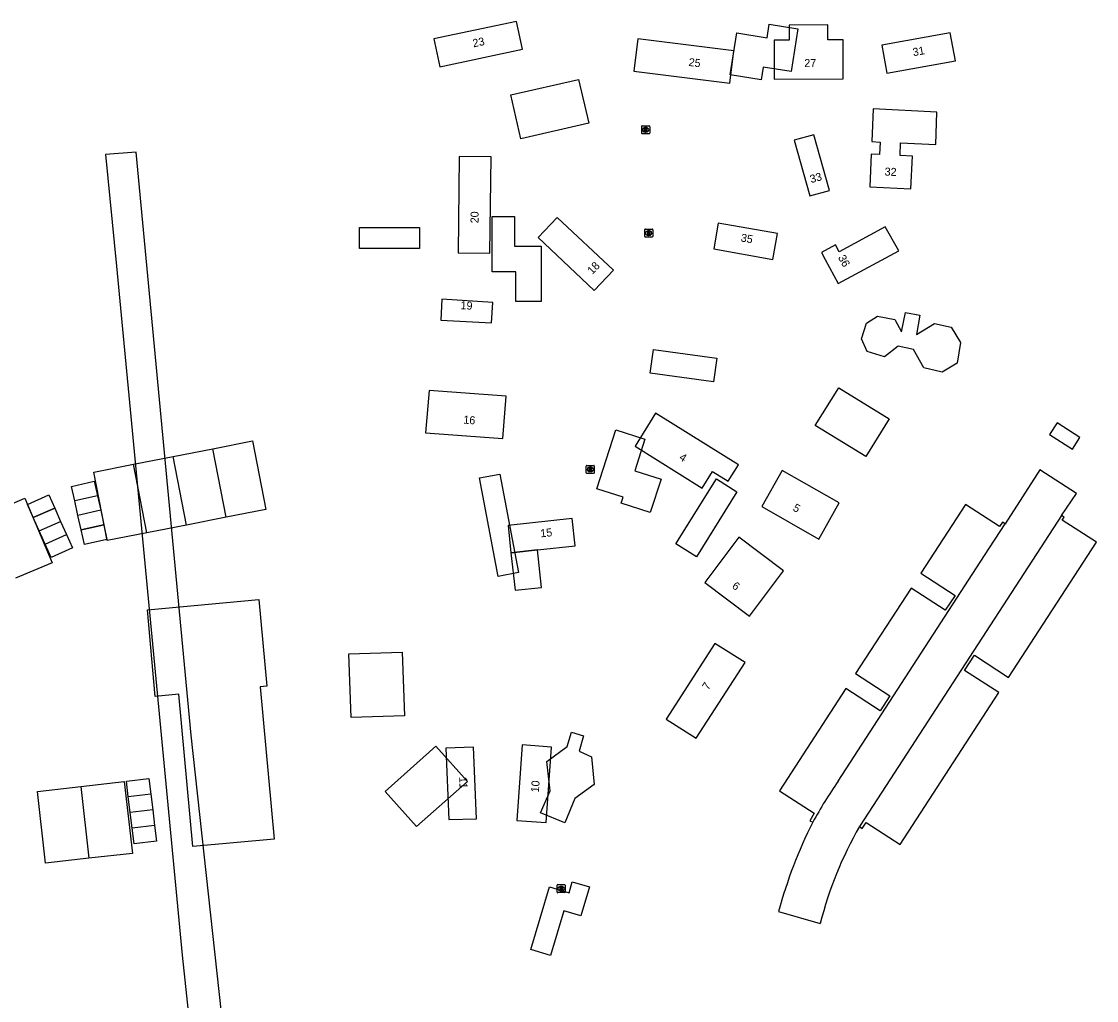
# Model space of a CAD drawing. Extents: x 159451 to 160663, y 388402 to 389723.
# Drawn here: x 160018.5 to 160152.8, y 389378.7 to 389501 of the extents above; entities that cross this region are included whole.
import ezdxf

# ---------------------------------------------------------------- set-up
doc = ezdxf.new("R2010")
doc.units = 0
for name, color, linetype in [('IMGEO_Lage_trafo', 7, 'Continuous'), ('IMGEO_Pand', 7, 'Continuous'), ('IMGEO_Pand_nummerreeks', 7, 'Continuous'), ('IMGEO_Pand_overbouw', 7, 'Continuous'), ('IMGEO_Pand_vergunning_verleend', 7, 'Continuous'), ('IMGEO_Parkeervlak_halfverhard', 7, 'Continuous'), ('IMGEO_Rijbaan_lokaal_gesloten', 7, 'Continuous'), ('IMGEO_Rioolput', 7, 'Continuous'), ('IMGEO_Voetpad_open', 7, 'Continuous')]:
    doc.layers.add(name, color=color, linetype=linetype)

msp = doc.modelspace()

# ---------------------------------------------------------------- linework, layer by layer
at = {"layer": 'IMGEO_Lage_trafo'}
msp.add_lwpolyline([(160147.91, 389450.86), (160146.97, 389449.39), (160149.82, 389447.57), (160150.76, 389449.03), (160147.91, 389450.86)], dxfattribs=at)
at = {"layer": 'IMGEO_Pand'}
for points in [[(160080.36, 389501), (160070.05, 389498.84), (160070.78, 389495.34), (160081.12, 389497.53), (160080.36, 389501)], [(160121.17, 389498.71), (160119.29, 389498.71), (160119.29, 389500.59), (160114.43, 389500.55), (160114.43, 389498.66), (160112.55, 389498.67), (160112.55, 389493.81), (160121.17, 389493.82), (160121.17, 389498.71)], [(160107.52, 389497.34), (160095.55, 389498.83), (160095.05, 389494.8), (160107.02, 389493.3), (160107.52, 389497.34)], [(160126.65, 389494.53), (160135.2, 389496.09), (160134.56, 389499.6), (160126, 389498.04), (160126.65, 389494.53)], [(160128.36, 389485.84), (160132.76, 389485.65), (160132.88, 389489.68), (160124.95, 389490.08), (160124.77, 389485.99), (160125.81, 389485.94), (160125.74, 389484.37), (160124.7, 389484.42), (160124.52, 389480.33), (160129.66, 389480.11), (160129.84, 389484.19), (160128.29, 389484.26), (160128.36, 389485.84)], [(160119.49, 389479.88), (160117.54, 389486.85), (160115.08, 389486.18), (160117.02, 389479.2), (160119.49, 389479.88)], [(160077.21, 389484.09), (160073.22, 389484.14), (160073.08, 389472.08), (160077.05, 389472.05), (160077.21, 389484.09)], [(160085.45, 389476.52), (160083.08, 389474.01), (160090.07, 389467.39), (160092.47, 389469.92), (160085.45, 389476.52)], [(160112.97, 389474.51), (160105.57, 389475.82), (160105.01, 389472.59), (160112.39, 389471.28), (160112.97, 389474.51)], [(160126.43, 389475.36), (160120.68, 389472.23), (160120.22, 389473.09), (160118.48, 389472.14), (160118.93, 389471.27), (160120.58, 389468.25), (160128.12, 389472.33), (160126.43, 389475.36)], [(160077.41, 389465.88), (160071.03, 389466.3), (160070.91, 389463.7), (160077.24, 389463.34), (160077.41, 389465.88)], [(160079.09, 389454.17), (160069.44, 389454.87), (160069, 389449.6), (160078.65, 389448.89), (160079.09, 389454.17)], [(160095.18, 389447.92), (160103.57, 389442.69), (160104.87, 389444.76), (160106.81, 389443.57), (160108.09, 389445.62), (160097.75, 389452.04), (160095.18, 389447.92)], [(160113.58, 389444.9), (160111.01, 389440.4), (160118.14, 389436.32), (160120.69, 389440.86), (160113.58, 389444.9)], [(160079.31, 389438), (160079.68, 389434.62), (160082.99, 389434.98), (160087.7, 389435.49), (160087.34, 389438.88), (160079.31, 389438)], [(160113.73, 389432.37), (160108.13, 389436.56), (160103.89, 389430.89), (160109.49, 389426.71), (160113.73, 389432.37)], [(160108.93, 389420.88), (160105.14, 389423.28), (160099.07, 389413.81), (160102.83, 389411.44), (160108.93, 389420.88)], [(160071.92, 389401.26), (160075.38, 389401.38), (160075, 389410.33), (160071.54, 389410.21), (160071.92, 389401.26)], [(160084.74, 389410.32), (160081.08, 389410.59), (160080.4, 389401.16), (160084.06, 389400.9), (160084.74, 389410.32)]]:
    msp.add_lwpolyline(points, dxfattribs=at)
at = {"layer": 'IMGEO_Pand_overbouw'}
msp.add_lwpolyline([(160079.68, 389434.62), (160080.2, 389429.92), (160083.51, 389430.28), (160082.99, 389434.98)], close=True, dxfattribs=at)
at = {"layer": 'IMGEO_Pand_vergunning_verleend'}
for points in [[(160107.07, 389494.35), (160107.91, 389499.58), (160111.68, 389498.97), (160111.96, 389500.66), (160115.54, 389500.08), (160114.7, 389494.74), (160111.21, 389495.31), (160110.95, 389493.72), (160107.07, 389494.35)], [(160079.66, 389491.82), (160088.13, 389493.75), (160089.39, 389488.28), (160080.91, 389486.34), (160079.66, 389491.82)], [(160077.31, 389469.71), (160077.31, 389476.64), (160080.12, 389476.64), (160080.12, 389472.92), (160083.45, 389472.92), (160083.45, 389466.01), (160080.27, 389466.01), (160080.27, 389469.71), (160077.31, 389469.71)], [(160060.77, 389472.65), (160060.77, 389475.25), (160068.23, 389475.27), (160068.23, 389472.65), (160060.77, 389472.65)], [(160123.48, 389461.35), (160124.1, 389463.32), (160125.48, 389464.19), (160127.64, 389463.76), (160128.49, 389462.24), (160128.96, 389464.62), (160130.77, 389464.3), (160130.36, 389461.9), (160132.6, 389463.26), (160134.66, 389462.81), (160135.84, 389460.9), (160135.44, 389458.31), (160133.54, 389457.17), (160131.27, 389457.73), (160129.98, 389460.01), (160128.06, 389460.43), (160126.37, 389459.09), (160124.17, 389459.75), (160123.48, 389461.35)], [(160097.08, 389457.05), (160097.48, 389460.01), (160105.41, 389458.92), (160105, 389455.96), (160097.08, 389457.05)], [(160117.69, 389450.51), (160120.63, 389455.24), (160126.92, 389451.37), (160124, 389446.63), (160117.69, 389450.51)], [(160090.42, 389442.62), (160092.77, 389449.97), (160096.42, 389448.81), (160095.16, 389444.87), (160098.43, 389443.83), (160097.09, 389439.64), (160093.45, 389440.81), (160093.69, 389441.57), (160090.42, 389442.62)], [(160042.42, 389447.61), (160047.37, 389448.58), (160049.05, 389440.02), (160044.09, 389439.05)], [(160032.51, 389445.67), (160037.46, 389446.64)], [(160037.46, 389446.64), (160042.42, 389447.61)], [(160039.14, 389438.08), (160037.46, 389446.64)], [(160044.09, 389439.05), (160042.42, 389447.61)], [(160034.19, 389437.11), (160029.23, 389436.14), (160027.56, 389444.7), (160032.51, 389445.67)], [(160034.19, 389437.11), (160032.51, 389445.67)], [(160075.76, 389443.98), (160078.3, 389444.45), (160080.6, 389432.13), (160078.06, 389431.66), (160075.76, 389443.98)], [(160100.26, 389435.72), (160105.34, 389443.87), (160107.9, 389442.21), (160102.84, 389434.11), (160100.26, 389435.72)], [(160025.17, 389441.1), (160024.76, 389442.91), (160027.61, 389443.55), (160028.01, 389441.74)], [(160014.38, 389439.49), (160018.94, 389441.42), (160022.34, 389433.35), (160017.78, 389431.43)], [(160022.67, 389440.2), (160020, 389439.01), (160019.27, 389440.66), (160021.93, 389441.85), (160022.67, 389440.2)], [(160028.01, 389441.74), (160025.17, 389441.1)], [(160025.58, 389439.29), (160025.17, 389441.1)], [(160028.01, 389441.74), (160028.42, 389439.93)], [(160020.74, 389437.35), (160020, 389439), (160022.67, 389440.2)], [(160022.67, 389440.2), (160023.41, 389438.54)], [(160028.42, 389439.93), (160025.58, 389439.29)], [(160028.42, 389439.93), (160028.83, 389438.11), (160028.79, 389438.1)], [(160020.74, 389437.35), (160023.41, 389438.54)], [(160023.41, 389438.54), (160024.15, 389436.89)], [(160025.98, 389437.48), (160025.58, 389439.29)], [(160044.09, 389439.05), (160039.14, 389438.08)], [(160021.48, 389435.69), (160020.74, 389437.35)], [(160025.98, 389437.48), (160028.79, 389438.11), (160028.79, 389438.1)], [(160028.79, 389438.1), (160025.98, 389437.48)], [(160028.79, 389438.1), (160029.2, 389436.29), (160026.39, 389435.66), (160025.98, 389437.48)], [(160039.14, 389438.08), (160034.19, 389437.11)], [(160021.48, 389435.69), (160024.15, 389436.89)], [(160024.15, 389436.89), (160024.89, 389435.23), (160022.22, 389434.04), (160021.48, 389435.69)], [(160034.25, 389427.5), (160048.19, 389428.77), (160049.18, 389417.94), (160048.35, 389417.87), (160050.09, 389398.82), (160039.93, 389397.89), (160038.18, 389416.94), (160035.24, 389416.67), (160034.25, 389427.5)], [(160059.42, 389421.97), (160066.08, 389422.21), (160066.36, 389414.25), (160059.7, 389414.02), (160059.42, 389421.97)], [(160083.38, 389402.1), (160084.57, 389404.86), (160084.15, 389408.54), (160086.71, 389410.41), (160087.25, 389412.18), (160088.76, 389411.72), (160088.18, 389409.8), (160089.75, 389409.11), (160090.07, 389405.65), (160087.66, 389403.89), (160086.42, 389400.85), (160083.38, 389402.1)], [(160063.97, 389404.79), (160070.3, 389410.44), (160074.23, 389406.04), (160067.89, 389400.39), (160063.97, 389404.79)], [(160031.87, 389404.12), (160031.63, 389406.07), (160034.45, 389406.41), (160034.68, 389404.46)], [(160026.95, 389396.44), (160021.53, 389395.83), (160020.52, 389404.79), (160025.95, 389405.4)], [(160025.95, 389405.4), (160031.37, 389406.01), (160032.38, 389397.05), (160026.95, 389396.44)], [(160025.95, 389405.4), (160026.95, 389396.44)], [(160034.68, 389404.46), (160031.87, 389404.12)], [(160032.11, 389402.16), (160031.87, 389404.12)], [(160034.68, 389404.46), (160034.92, 389402.5)], [(160034.92, 389402.5), (160032.11, 389402.16)], [(160032.34, 389400.2), (160032.11, 389402.16)], [(160034.92, 389402.5), (160035.16, 389400.55)], [(160035.16, 389400.55), (160032.34, 389400.2)], [(160035.16, 389400.55), (160035.39, 389398.59), (160032.58, 389398.25), (160032.34, 389400.2)], [(160082.16, 389385.02), (160084.48, 389392.85), (160086.93, 389392.13), (160087.34, 389393.51), (160089.5, 389392.87), (160088.42, 389389.23), (160086.29, 389389.86), (160084.63, 389384.28), (160082.16, 389385.02)]]:
    msp.add_lwpolyline(points, dxfattribs=at)
at = {"layer": 'IMGEO_Parkeervlak_halfverhard'}
for points in [[(160141.43, 389438.23), (160141.1, 389438.45), (160140.71, 389437.9), (160136.47, 389440.66), (160130.89, 389432.05), (160135.17, 389429.29), (160133.95, 389427.42), (160129.68, 389430.2), (160122.74, 389419.51), (160127.01, 389416.74), (160125.79, 389414.87), (160121.53, 389417.63), (160113.22, 389404.87), (160117.57, 389402.08), (160117.03, 389401.12), (160117.38, 389400.94)], [(160123.21, 389400.4), (160123.57, 389400.17), (160124.05, 389400.89), (160128.3, 389398.15), (160140.62, 389417.13), (160136.36, 389419.9), (160137.6, 389421.81), (160141.86, 389419.02), (160152.84, 389435.93), (160148.56, 389438.7), (160148.79, 389439.07), (160148.48, 389439.26)]]:
    msp.add_lwpolyline(points, dxfattribs=at)
at = {"layer": 'IMGEO_Rijbaan_lokaal_gesloten'}
for points in [[(160148.48, 389439.26), (160150.34, 389442.02), (160145.75, 389444.96), (160141.43, 389438.23)], [(160148.48, 389439.26), (160125.49, 389403.86), (160123.21, 389400.4)], [(160120.55, 389406.08), (160138.83, 389434.26), (160141.43, 389438.23)], [(160113.12, 389389.79), (160118.33, 389388.29)]]:
    msp.add_lwpolyline(points, dxfattribs=at)
for centre, radius, start, end in [((160168.1, 389373.19), 57.81, 145.3299, 151.3171), ((160170.72, 389374.2), 59.67, 153.3759, 164.8558), ((160164.95, 389376.5), 48.09, 150.2054, 165.8137)]:
    msp.add_arc(centre, radius, start, end, dxfattribs=at)
at = {"layer": 'IMGEO_Rioolput'}
for p, q in [((160096.01, 389487.05), (160096.01, 389487.9)), ((160096.08, 389487.97), (160096.93, 389487.97)), ((160096.93, 389486.97), (160096.08, 389486.97)), ((160096.52, 389487.19), (160096.49, 389487.19)), ((160096.5, 389487.75), (160096.52, 389487.75)), ((160097.01, 389487.9), (160097.01, 389487.05)), ((160096.39, 389474.13), (160096.39, 389474.99)), ((160096.46, 389475.06), (160097.32, 389475.06)), ((160096.88, 389474.84), (160096.9, 389474.84)), ((160097.39, 389474.99), (160097.39, 389474.13)), ((160097.32, 389474.06), (160096.46, 389474.06)), ((160096.9, 389474.28), (160096.87, 389474.28)), ((160089.09, 389444.6), (160089.09, 389445.45)), ((160089.16, 389445.53), (160090.01, 389445.53)), ((160089.57, 389445.31), (160089.6, 389445.31)), ((160090.09, 389445.45), (160090.09, 389444.6)), ((160090.01, 389444.53), (160089.16, 389444.53)), ((160089.6, 389444.75), (160089.57, 389444.75)), ((160085.44, 389392.21), (160085.44, 389393.06)), ((160085.52, 389393.14), (160086.37, 389393.14)), ((160085.93, 389392.92), (160085.96, 389392.92)), ((160086.45, 389393.06), (160086.45, 389392.21)), ((160086.37, 389392.14), (160085.52, 389392.14)), ((160085.95, 389392.36), (160085.93, 389392.36))]:
    msp.add_line(p, q, dxfattribs=at)
for points in [[(160096.01, 389487.05), (160096.01, 389487.9)], [(160096.08, 389487.97), (160096.93, 389487.97)], [(160096.93, 389486.97), (160096.08, 389486.97)], [(160096.6, 389487.67), (160096.34, 389487.67), (160096.34, 389487.27)], [(160096.34, 389487.27), (160096.47, 389487.27), (160096.47, 389487.43), (160096.48, 389487.43)], [(160096.52, 389487.59), (160096.47, 389487.59), (160096.47, 389487.51)], [(160096.47, 389487.51), (160096.52, 389487.51)], [(160096.53, 389487.4), (160096.6, 389487.27), (160096.74, 389487.27), (160096.67, 389487.4)], [(160097.01, 389487.9), (160097.01, 389487.05)], [(160096.39, 389474.13), (160096.39, 389474.99)], [(160096.46, 389475.06), (160097.32, 389475.06)], [(160096.98, 389474.76), (160096.73, 389474.76), (160096.73, 389474.36)], [(160096.9, 389474.68), (160096.85, 389474.68), (160096.85, 389474.6)], [(160097.39, 389474.99), (160097.39, 389474.13)], [(160097.32, 389474.06), (160096.46, 389474.06)], [(160096.73, 389474.36), (160096.85, 389474.36), (160096.85, 389474.52), (160096.86, 389474.52)], [(160096.85, 389474.6), (160096.9, 389474.6)], [(160096.91, 389474.49), (160096.98, 389474.36), (160097.12, 389474.36), (160097.05, 389474.49)], [(160089.09, 389444.6), (160089.09, 389445.45)], [(160089.16, 389445.53), (160090.01, 389445.53)], [(160089.68, 389445.22), (160089.42, 389445.23), (160089.42, 389444.83)], [(160089.6, 389445.15), (160089.55, 389445.15), (160089.55, 389445.06)], [(160090.09, 389445.45), (160090.09, 389444.6)], [(160090.01, 389444.53), (160089.16, 389444.53)], [(160089.42, 389444.83), (160089.55, 389444.83), (160089.55, 389444.99), (160089.56, 389444.99)], [(160089.55, 389445.06), (160089.6, 389445.06)], [(160089.6, 389444.96), (160089.68, 389444.83), (160089.82, 389444.83), (160089.75, 389444.95)], [(160085.44, 389392.21), (160085.44, 389393.06)], [(160085.52, 389393.14), (160086.37, 389393.14)], [(160086.03, 389392.83), (160085.78, 389392.84), (160085.78, 389392.44)], [(160085.96, 389392.76), (160085.91, 389392.76), (160085.91, 389392.67)], [(160086.45, 389393.06), (160086.45, 389392.21)], [(160086.37, 389392.14), (160085.52, 389392.14)], [(160085.78, 389392.44), (160085.91, 389392.44), (160085.91, 389392.6), (160085.92, 389392.6)], [(160085.91, 389392.67), (160085.96, 389392.67)], [(160085.96, 389392.57), (160086.03, 389392.44), (160086.17, 389392.44), (160086.11, 389392.56)]]:
    msp.add_lwpolyline(points, dxfattribs=at)
for centre, radius, start, end in [((160096.08, 389487.9), 0.0765, 91.552, 178.448), ((160096.08, 389487.9), 0.0765, 91.552, 178.448), ((160096.08, 389487.05), 0.0765, 181.552, 268.448), ((160096.08, 389487.05), 0.0765, 181.552, 268.448), ((160096.48, 389487.38), 0.0533, 26.0293, 88.6989), ((160096.53, 389487.49), 0.0964, 77.0061, 93.1865), ((160096.5, 389487.7), 0.19, 274.7715, 282.9687), ((160096.54, 389487.55), 0.0378, 276.6634, 79.6772), ((160096.6, 389487.56), 0.109, 350.3612, 89.416), ((160096.59, 389487.56), 0.112, 277.5842, 350.9817), ((160096.58, 389487.34), 0.108, 29.5134, 73.7905), ((160096.93, 389487.9), 0.0765, 1.552, 88.448), ((160096.93, 389487.9), 0.0765, 1.552, 88.448), ((160096.93, 389487.05), 0.0765, 271.552, 358.448), ((160096.93, 389487.05), 0.0765, 271.552, 358.448), ((160096.47, 389474.98), 0.0765, 91.552, 178.448), ((160096.47, 389474.98), 0.0765, 91.552, 178.448), ((160096.91, 389474.58), 0.0964, 77.0061, 93.1865), ((160096.92, 389474.64), 0.0378, 276.6634, 79.6772), ((160096.98, 389474.65), 0.109, 350.3612, 89.416), ((160097.31, 389474.98), 0.0765, 1.552, 88.448), ((160097.31, 389474.98), 0.0765, 1.552, 88.448), ((160096.47, 389474.13), 0.0765, 181.552, 268.448), ((160096.47, 389474.13), 0.0765, 181.552, 268.448), ((160096.86, 389474.47), 0.0533, 26.0293, 88.6989), ((160096.89, 389474.79), 0.19, 274.7715, 282.9687), ((160096.98, 389474.65), 0.112, 277.5842, 350.9817), ((160096.96, 389474.43), 0.108, 29.5134, 73.7905), ((160097.31, 389474.13), 0.0765, 271.552, 358.448), ((160097.31, 389474.13), 0.0765, 271.552, 358.448), ((160089.16, 389445.45), 0.0765, 91.552, 178.448), ((160089.16, 389445.45), 0.0765, 91.552, 178.448), ((160089.61, 389445.05), 0.0964, 77.0061, 93.1865), ((160089.62, 389445.11), 0.0378, 276.6634, 79.6772), ((160089.67, 389445.11), 0.109, 350.3612, 89.416), ((160090.01, 389445.45), 0.0765, 1.552, 88.448), ((160090.01, 389445.45), 0.0765, 1.552, 88.448), ((160089.16, 389444.6), 0.0765, 181.552, 268.448), ((160089.16, 389444.6), 0.0765, 181.552, 268.448), ((160089.56, 389444.94), 0.0533, 26.0293, 88.6989), ((160089.58, 389445.25), 0.19, 274.7715, 282.9687), ((160089.67, 389445.11), 0.112, 277.5842, 350.9817), ((160089.66, 389444.9), 0.108, 29.5134, 73.7905), ((160090.01, 389444.6), 0.0765, 271.552, 358.448), ((160090.01, 389444.6), 0.0765, 271.552, 358.448), ((160085.52, 389393.06), 0.0765, 91.552, 178.448), ((160085.52, 389393.06), 0.0765, 91.552, 178.448), ((160085.96, 389392.66), 0.0964, 77.0061, 93.1865), ((160085.98, 389392.72), 0.0378, 276.6634, 79.6772), ((160086.03, 389392.72), 0.109, 350.3612, 89.416), ((160086.37, 389393.06), 0.0765, 1.552, 88.448), ((160086.37, 389393.06), 0.0765, 1.552, 88.448), ((160085.52, 389392.21), 0.0765, 181.552, 268.448), ((160085.52, 389392.21), 0.0765, 181.552, 268.448), ((160085.91, 389392.55), 0.0533, 26.0293, 88.6989), ((160085.94, 389392.86), 0.19, 274.7715, 282.9687), ((160086.03, 389392.72), 0.112, 277.5842, 350.9817), ((160086.01, 389392.51), 0.108, 29.5134, 73.7905), ((160086.37, 389392.21), 0.0765, 271.552, 358.448), ((160086.37, 389392.21), 0.0765, 271.552, 358.448)]:
    msp.add_arc(centre, radius, start, end, dxfattribs=at)
for centre, major_axis, ratio, start_param, end_param in [((160096.49, 389487.47), (-0.387, 0.002), 0.722429, 4.712389, 7.853982), ((160096.52, 389487.47), (-0.39, 0.002), 0.717154, 1.570796, 4.712389), ((160096.88, 389474.56), (-0.387, 0.002), 0.722429, 4.712389, 7.853982), ((160096.9, 389474.56), (-0.39, 0.002), 0.717154, 1.570796, 4.712389), ((160089.57, 389445.03), (-0.387, 0.002), 0.722429, 4.712389, 7.853982), ((160089.6, 389445.03), (-0.39, 0.002), 0.717154, 1.570796, 4.712389), ((160085.93, 389392.64), (-0.387, 0.002), 0.722429, 4.712389, 7.853982), ((160085.96, 389392.64), (-0.39, 0.002), 0.717154, 1.570796, 4.712389)]:
    msp.add_ellipse(centre, major_axis=major_axis, ratio=ratio, start_param=start_param, end_param=end_param, dxfattribs=at)
at = {"layer": 'IMGEO_Voetpad_open'}
msp.add_lwpolyline([(160045.57, 389377.18), (160043.52, 389377.12), (160039.74, 389411.81), (160032.85, 389484.66), (160029, 389484.38), (160030.41, 389470.42), (160038.58, 389384.31), (160039.49, 389376.11)], dxfattribs=at)

# ---------------------------------------------------------------- texts
at = {"layer": 'IMGEO_Pand_nummerreeks'}
for s, rotation, p in [('23', 11.9347, (160075, 389497.77)), ('31', 10.3935, (160129.97, 389496.66)), ('25', 352.8609, (160101.83, 389495.46)), ('27', 0.0974, (160116.33, 389495.31)), ('32', 357.4733, (160126.35, 389481.76)), ('33', 15.2922, (160117.18, 389480.8)), ('20', 89.3356, (160075.62, 389475.78)), ('35', 349.9331, (160108.34, 389473.53)), ('18', 46.6044, (160089.84, 389469.32)), ('36', 298.5102, (160120.51, 389471.51)), ('19', 356.7456, (160073.36, 389465.06)), ('16', 355.7544, (160073.7, 389450.76)), ('4', 328.0232, (160100.61, 389446.3)), ('5', 330.252, (160114.81, 389439.95)), ('15', 6.2624, (160083.4, 389436.53)), ('6', 323.2505, (160107.21, 389430.28)), ('7', 57.3473, (160104.33, 389417.38)), ('11', 272.4635, (160073.2, 389406.59)), ('10', 85.9036, (160083.16, 389404.64))]:
    msp.add_text(s, height=1, rotation=rotation, dxfattribs=at).set_placement(p)

doc.saveas('drawing.dxf')
